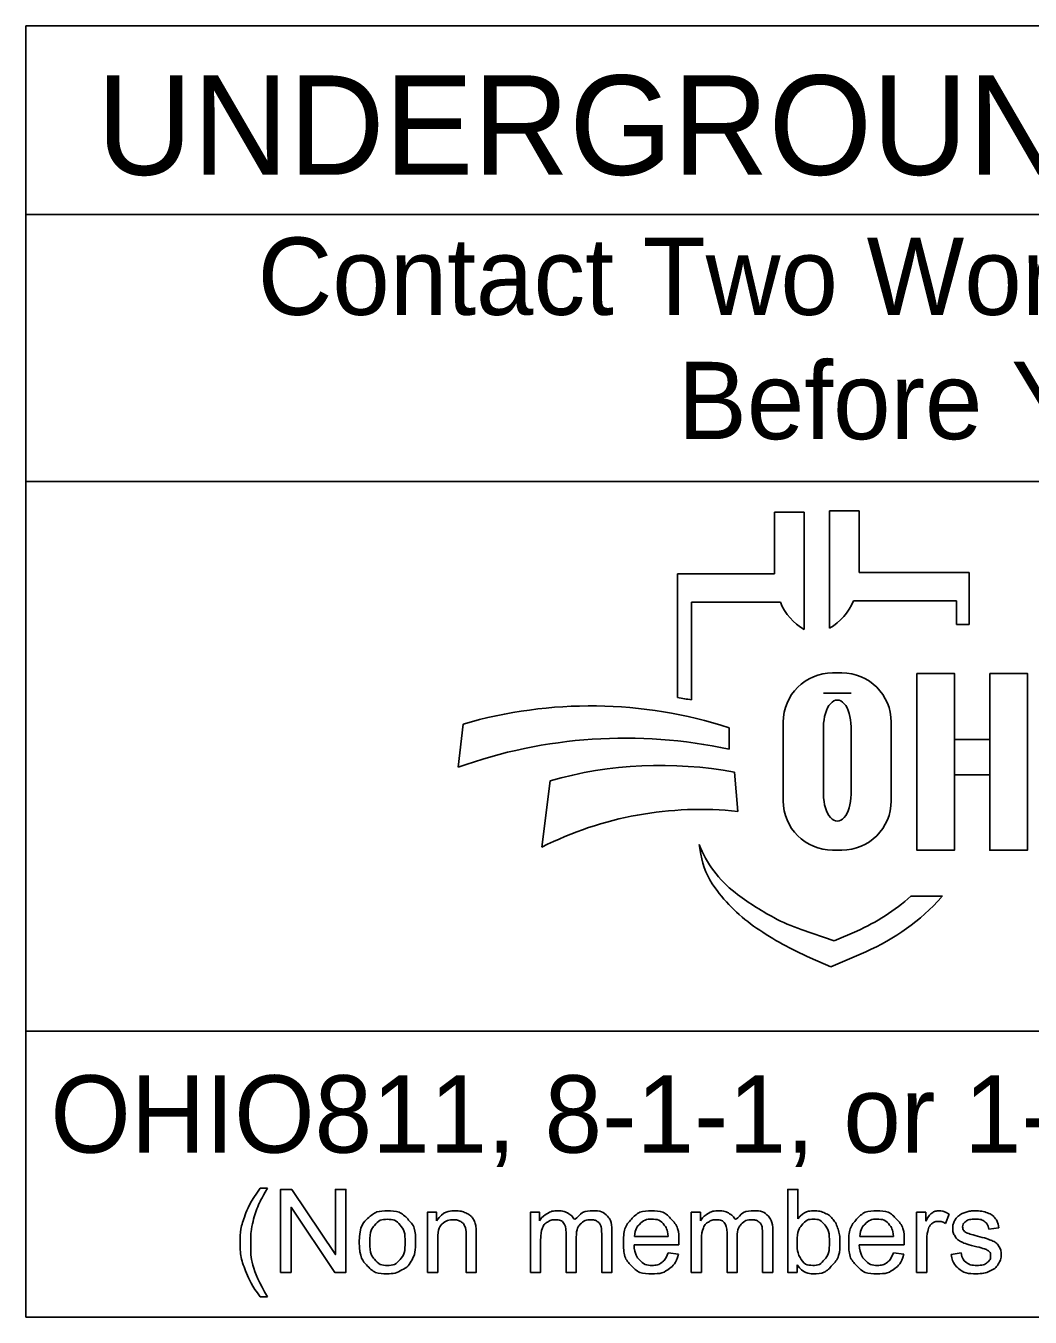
# Model space of a CAD drawing. Extents: x -8.3 to 42.1, y 0 to 22.
# Drawn here: x 2.378 to 4.196, y 2.143 to 4.48 of the extents above; entities that cross this region are included whole.
import ezdxf

# ---------------------------------------------------------------- set-up
doc = ezdxf.new("R2010")
doc.units = 0
doc.layers.add('SH_Data', color=7, linetype='Continuous')
doc.layers.add('SH_Text', color=7, linetype='Continuous')

msp = doc.modelspace()

# ---------------------------------------------------------------- linework, layer by layer
at = {"layer": 'SH_Data'}
for p, q in [((2.3775, 2.1428), (2.3775, 4.4803)), ((6.6275, 4.4803), (2.3775, 4.4803)), ((2.3775, 4.1387), (6.6275, 4.1387)), ((2.3775, 3.6553), (6.6275, 3.6553)), ((6.6275, 2.6607), (2.3775, 2.6607)), ((6.6275, 2.1428), (2.3775, 2.1428))]:
    msp.add_line(p, q, dxfattribs=at)
at = {"layer": 'SH_Text'}
for p, q in [((3.7335, 3.4883), (3.7335, 3.5998)), ((3.7335, 3.5998), (3.7872, 3.5998)), ((3.7872, 3.5998), (3.7872, 3.3877)), ((3.8329, 3.39), (3.8329, 3.6021)), ((3.8329, 3.6021), (3.8865, 3.6021)), ((3.8865, 3.6021), (3.8865, 3.4906)), ((3.5576, 3.2644), (3.5576, 3.4883)), ((3.5576, 3.4883), (3.7335, 3.4883)), ((3.8865, 3.4906), (4.0857, 3.4906)), ((4.0857, 3.4906), (4.0857, 3.3968)), ((3.5828, 3.4369), (3.5828, 3.26)), ((3.7439, 3.4369), (3.5828, 3.4369)), ((4.0625, 3.4392), (3.8761, 3.4392)), ((4.0625, 3.3968), (4.0625, 3.4392)), ((4.0857, 3.3968), (4.0625, 3.3968)), ((3.8385, 3.3091), (3.8551, 3.3091)), ((3.8718, 3.2721), (3.822, 3.2721)), ((3.1602, 3.1381), (3.1696, 3.2162)), ((3.6509, 3.2097), (3.6509, 3.1709)), ((3.7491, 3.0776), (3.7491, 3.2196)), ((3.822, 3.089), (3.822, 3.2114)), ((3.8718, 3.2114), (3.8718, 3.089)), ((3.9445, 3.2196), (3.9445, 3.0776)), ((3.312, 2.9936), (3.3267, 3.1137)), ((3.6608, 3.1291), (3.6671, 3.0582)), ((3.5997, 2.9807), (3.5967, 2.9986)), ((3.8551, 2.9882), (3.8385, 2.9882)), ((3.98, 2.9048), (4.0375, 2.9048)), ((3.7816, 2.8444), (3.841, 2.8239)), ((3.841, 2.8239), (3.8821, 2.8417)), ((3.835, 2.7769), (3.7976, 2.7934)), ((3.8983, 2.8044), (3.835, 2.7769))]:
    msp.add_line(p, q, dxfattribs=at)
for points in [[(3.991, 3.3081), (4.0589, 3.3081), (4.0589, 2.9881), (3.991, 2.9881)], [(4.1231, 3.3081), (4.1911, 3.3081), (4.1911, 2.9881), (4.1231, 2.9881)], [(4.0589, 3.1882), (4.1231, 3.1882), (4.1231, 3.1242), (4.0589, 3.1242)]]:
    msp.add_lwpolyline(points, close=True, dxfattribs=at)
for points in [[(2.8021, 2.3766), (2.8153, 2.3766)], [(2.8389, 2.2239), (2.8389, 2.3741), (2.8592, 2.3741), (2.9382, 2.2561), (2.9382, 2.3741), (2.9572, 2.3741), (2.9572, 2.2239), (2.9369, 2.2239), (2.8579, 2.3419), (2.8579, 2.2239), (2.8389, 2.2239)], [(3.7743, 2.2239), (3.7573, 2.2239), (3.7573, 2.3741), (3.7757, 2.3741), (3.7757, 2.3206)], [(3.1048, 2.2239), (3.1048, 2.3328), (3.1214, 2.3328), (3.1214, 2.3173)], [(3.2912, 2.2239), (3.2912, 2.3328), (3.3077, 2.3328), (3.3077, 2.3174)], [(3.5826, 2.2239), (3.5826, 2.3328), (3.5991, 2.3328), (3.5991, 2.3174)], [(3.9904, 2.2239), (3.9904, 2.3328), (4.007, 2.3328), (4.007, 2.3163)], [(4.0495, 2.3293), (4.043, 2.3122)], [(3.1932, 2.2908), (3.1932, 2.2239), (3.1748, 2.2239), (3.1748, 2.2901)], [(3.3743, 2.2871), (3.3743, 2.2239), (3.3559, 2.2239), (3.3559, 2.2946)], [(3.4388, 2.2986), (3.4388, 2.2239), (3.4203, 2.2239), (3.4203, 2.2924)], [(3.6657, 2.2871), (3.6657, 2.2239), (3.6473, 2.2239), (3.6473, 2.2946)], [(3.7301, 2.2986), (3.7301, 2.2239), (3.7117, 2.2239), (3.7117, 2.2924)], [(4.1394, 2.3046), (4.1213, 2.3022)], [(3.1233, 2.2833), (3.1233, 2.2239), (3.1048, 2.2239)], [(3.3097, 2.2803), (3.3097, 2.2239), (3.2912, 2.2239)], [(3.56, 2.2736), (3.4788, 2.2736)], [(3.4799, 2.2887), (3.5406, 2.2887)], [(3.601, 2.2803), (3.601, 2.2239), (3.5826, 2.2239)], [(3.968, 2.2736), (3.8868, 2.2736)], [(3.8879, 2.2887), (3.9486, 2.2887)], [(4.0088, 2.2809), (4.0088, 2.2239), (3.9904, 2.2239)], [(3.5404, 2.2591), (3.5595, 2.2567)], [(3.9484, 2.2591), (3.9675, 2.2567)], [(4.053, 2.2564), (4.0712, 2.2593)], [(3.7743, 2.2375), (3.7743, 2.2239)], [(2.8153, 2.1798), (2.8021, 2.1798)]]:
    msp.add_lwpolyline(points, dxfattribs=at)
for centre, radius, start, end in [((3.8353, 3.4736), 0.0985, 201.9296, 240.7469), ((3.7847, 3.476), 0.0985, 299.2531, 338.0704), ((3.8385, 3.2196), 0.0895, 90, 180), ((3.8551, 3.2196), 0.0895, 0, 90), ((3.3997, 2.4302), 0.8191, 72.1402, 106.3144), ((3.4295, 2.4554), 0.8191, 79.2074, 81.0007), ((3.4628, 2.2991), 0.8919, 77.8238, 109.8274), ((3.5267, 2.4094), 0.7322, 79.44, 105.8467), ((3.8385, 3.0776), 0.0895, 180, 270), ((3.8551, 3.0776), 0.0895, 270, 0), ((3.5987, 2.4262), 0.6357, 83.8248, 116.8021), ((3.7841, 3.0707), 0.2008, 201.0457, 232.5314), ((3.741, 3.0048), 0.1433, 189.6817, 216.0884), ((3.8747, 3.1022), 0.3088, 216.0884, 235.7167), ((3.9766, 3.3219), 0.5173, 232.5314, 241.794), ((3.7387, 3.1722), 0.3602, 293.4582, 312.0712), ((3.7387, 3.1722), 0.401, 293.4582, 317.8286), ((3.8914, 3.1631), 0.3371, 241.794, 250.9821), ((4.0412, 3.3465), 0.6044, 235.7167, 246.2325)]:
    msp.add_arc(centre, radius, start, end, dxfattribs=at)
for centre, start_param, end_param in [((3.8469, 3.2114), 4.712389, 7.853982), ((3.8469, 3.089), 1.570796, 4.712389)]:
    msp.add_ellipse(centre, major_axis=(0, 0.0484), ratio=0.514403, start_param=start_param, end_param=end_param, dxfattribs=at)
for points in [[(2.8021, 2.1798), (2.7869, 2.199), (2.7763, 2.2248), (2.7657, 2.2506), (2.7657, 2.2783), (2.7657, 2.3026), (2.7736, 2.325), (2.7829, 2.3509), (2.8021, 2.3766)], [(2.8153, 2.3766), (2.8029, 2.3553), (2.7989, 2.3462), (2.7927, 2.332), (2.7891, 2.3167), (2.7847, 2.2975), (2.7847, 2.2782), (2.7847, 2.2289), (2.8153, 2.1798)], [(2.9814, 2.2783), (2.9814, 2.3085), (2.9981, 2.3231), (3.0122, 2.3352), (3.0323, 2.3352), (3.0547, 2.3352), (3.069, 2.3205), (3.0832, 2.3058), (3.0832, 2.2799), (3.0832, 2.2589), (3.0769, 2.2469), (3.0706, 2.2348), (3.0586, 2.2282), (3.0466, 2.2215), (3.0323, 2.2215), (3.0095, 2.2215), (2.9954, 2.2362), (2.9814, 2.2508), (2.9814, 2.2783)], [(3.0003, 2.2783), (3.0003, 2.2574), (3.0094, 2.247), (3.0185, 2.2366), (3.0323, 2.2366), (3.046, 2.2366), (3.0551, 2.2471), (3.0642, 2.2575), (3.0642, 2.279), (3.0642, 2.2991), (3.0551, 2.3095), (3.0459, 2.3199), (3.0323, 2.3199), (3.0185, 2.3199), (3.0094, 2.3096), (3.0003, 2.2992), (3.0003, 2.2783)], [(3.1214, 2.3173), (3.1334, 2.3352), (3.156, 2.3352), (3.1659, 2.3352), (3.1741, 2.3316), (3.1823, 2.3281), (3.1864, 2.3224), (3.1905, 2.3166), (3.1922, 2.3087), (3.1932, 2.3036), (3.1932, 2.2908)], [(3.1748, 2.2901), (3.1748, 2.3013), (3.1726, 2.3069), (3.1705, 2.3125), (3.165, 2.3158), (3.1595, 2.3191), (3.1521, 2.3191), (3.1404, 2.3191), (3.1318, 2.3117), (3.1233, 2.3042), (3.1233, 2.2833)], [(3.3077, 2.3174), (3.3128, 2.3254), (3.3214, 2.3303), (3.3299, 2.3352), (3.3407, 2.3352), (3.3528, 2.3352), (3.3606, 2.3301), (3.3683, 2.3251), (3.3715, 2.3161), (3.3844, 2.3352), (3.4051, 2.3352), (3.4213, 2.3352), (3.43, 2.3262), (3.4388, 2.3172), (3.4388, 2.2986)], [(3.3559, 2.2946), (3.3559, 2.3069), (3.3514, 2.313), (3.3469, 2.3191), (3.3366, 2.3191), (3.3288, 2.3191), (3.3222, 2.315), (3.3156, 2.311), (3.3126, 2.3031), (3.3097, 2.2952), (3.3097, 2.2803)], [(3.4203, 2.2924), (3.4203, 2.3035), (3.4185, 2.3083), (3.4168, 2.3132), (3.412, 2.3162), (3.4073, 2.3191), (3.401, 2.3191), (3.3895, 2.3191), (3.3819, 2.3115), (3.3743, 2.3039), (3.3743, 2.2871)], [(3.5595, 2.2567), (3.555, 2.24), (3.5428, 2.2307), (3.5306, 2.2215), (3.5117, 2.2215), (3.4878, 2.2215), (3.4738, 2.2362), (3.4598, 2.2509), (3.4598, 2.2774), (3.4598, 2.3049), (3.474, 2.32), (3.4881, 2.3352), (3.5106, 2.3352), (3.5324, 2.3352), (3.5463, 2.3203), (3.5601, 2.3055), (3.5601, 2.2785), (3.5601, 2.2769), (3.56, 2.2736)], [(3.5406, 2.2887), (3.5394, 2.3025), (3.5337, 2.3094), (3.5249, 2.3201), (3.5108, 2.3201), (3.4981, 2.3201), (3.4894, 2.3115), (3.4808, 2.303), (3.4799, 2.2887)], [(3.5991, 2.3174), (3.6042, 2.3254), (3.6127, 2.3303), (3.6212, 2.3352), (3.6321, 2.3352), (3.6442, 2.3352), (3.6519, 2.3301), (3.6597, 2.3251), (3.6628, 2.3161), (3.6758, 2.3352), (3.6965, 2.3352), (3.7127, 2.3352), (3.7214, 2.3262), (3.7301, 2.3172), (3.7301, 2.2986)], [(3.6473, 2.2946), (3.6473, 2.3069), (3.6428, 2.313), (3.6383, 2.3191), (3.628, 2.3191), (3.6202, 2.3191), (3.6136, 2.315), (3.607, 2.311), (3.604, 2.3031), (3.601, 2.2952), (3.601, 2.2803)], [(3.7117, 2.2924), (3.7117, 2.3035), (3.7099, 2.3083), (3.7081, 2.3132), (3.7034, 2.3162), (3.6987, 2.3191), (3.6923, 2.3191), (3.6809, 2.3191), (3.6733, 2.3115), (3.6657, 2.3039), (3.6657, 2.2871)], [(3.7741, 2.2792), (3.7741, 2.2596), (3.7794, 2.2509), (3.7881, 2.2366), (3.8029, 2.2366), (3.815, 2.2366), (3.8238, 2.2471), (3.8326, 2.2576), (3.8326, 2.2784), (3.8326, 2.2998), (3.8241, 2.3099), (3.8157, 2.3201), (3.8038, 2.3201), (3.7917, 2.3201), (3.7829, 2.3096), (3.7741, 2.299), (3.7741, 2.2792)], [(3.7757, 2.3206), (3.7874, 2.3352), (3.8055, 2.3352), (3.8155, 2.3352), (3.8245, 2.3311), (3.8335, 2.3271), (3.8392, 2.3198), (3.845, 2.3124), (3.8483, 2.3021), (3.8516, 2.2918), (3.8516, 2.28), (3.8516, 2.252), (3.8378, 2.2368), (3.8239, 2.2215), (3.8046, 2.2215), (3.7853, 2.2215), (3.7743, 2.2375)], [(3.9675, 2.2567), (3.963, 2.24), (3.9508, 2.2307), (3.9386, 2.2215), (3.9196, 2.2215), (3.8958, 2.2215), (3.8818, 2.2362), (3.8678, 2.2509), (3.8678, 2.2774), (3.8678, 2.3049), (3.882, 2.32), (3.8961, 2.3352), (3.9186, 2.3352), (3.9404, 2.3352), (3.9543, 2.3203), (3.9681, 2.3055), (3.9681, 2.2785), (3.9681, 2.2769), (3.968, 2.2736)], [(3.9486, 2.2887), (3.9474, 2.3025), (3.9417, 2.3094), (3.9328, 2.3201), (3.9188, 2.3201), (3.9061, 2.3201), (3.8974, 2.3115), (3.8888, 2.303), (3.8879, 2.2887)], [(4.007, 2.3163), (4.0133, 2.3278), (4.0187, 2.3315), (4.0241, 2.3352), (4.0305, 2.3352), (4.0398, 2.3352), (4.0495, 2.3293)], [(4.043, 2.3122), (4.0363, 2.3162), (4.0295, 2.3162), (4.0235, 2.3162), (4.0187, 2.3125), (4.0139, 2.3089), (4.0119, 2.3024), (4.0088, 2.2926), (4.0088, 2.2809)], [(4.1213, 2.3022), (4.1201, 2.3106), (4.1142, 2.3153), (4.1083, 2.3201), (4.0975, 2.3201), (4.0848, 2.3201), (4.0794, 2.3159), (4.0739, 2.3116), (4.0739, 2.306), (4.0739, 2.3024), (4.0762, 2.2995), (4.0785, 2.2966), (4.0833, 2.2946), (4.086, 2.2936), (4.0996, 2.2899), (4.1192, 2.2847), (4.1269, 2.2813), (4.1347, 2.278), (4.1391, 2.2717), (4.1435, 2.2653), (4.1435, 2.2559), (4.1435, 2.2467), (4.1381, 2.2386), (4.1327, 2.2304), (4.1226, 2.226), (4.1124, 2.2215), (4.0996, 2.2215), (4.0784, 2.2215), (4.0672, 2.2303), (4.0561, 2.2391), (4.053, 2.2564)], [(4.0712, 2.2593), (4.0727, 2.2483), (4.0798, 2.2425), (4.0868, 2.2366), (4.0995, 2.2366), (4.1122, 2.2366), (4.1184, 2.2418), (4.1245, 2.247), (4.1245, 2.254), (4.1245, 2.2602), (4.1191, 2.2638), (4.1153, 2.2663), (4.1002, 2.2701), (4.0799, 2.2752), (4.072, 2.2789), (4.0642, 2.2827), (4.0601, 2.2893), (4.0561, 2.2959), (4.0561, 2.3038), (4.0561, 2.3111), (4.0594, 2.3173), (4.0628, 2.3235), (4.0685, 2.3276), (4.0728, 2.3308), (4.0803, 2.333), (4.0877, 2.3352), (4.0962, 2.3352), (4.109, 2.3352), (4.1187, 2.3315), (4.1284, 2.3278), (4.133, 2.3215), (4.1377, 2.3152), (4.1394, 2.3046)], [(3.4788, 2.2736), (3.4799, 2.2557), (3.489, 2.2462), (3.4981, 2.2366), (3.5117, 2.2366), (3.5219, 2.2366), (3.5291, 2.242), (3.5362, 2.2473), (3.5404, 2.2591)], [(3.8868, 2.2736), (3.8879, 2.2557), (3.897, 2.2462), (3.9061, 2.2366), (3.9197, 2.2366), (3.9299, 2.2366), (3.937, 2.242), (3.9442, 2.2473), (3.9484, 2.2591)]]:
    msp.add_open_spline(points, degree=3, dxfattribs=at)

# ---------------------------------------------------------------- texts
for s, height, p in [('UNDERGROUND UTILITIES', 0.18, (2.5057, 4.2106)), ('Contact Two Working Days', 0.14, (2.7972, 3.9571)), ('Before You Dig', 0.14, (3.5583, 3.7321)), ('OHIO811, 8-1-1, or 1-800-362-2764', 0.14, (2.422, 2.4406))]:
    msp.add_text(s, height=height, dxfattribs=at).set_placement(p)

doc.saveas('drawing.dxf')
